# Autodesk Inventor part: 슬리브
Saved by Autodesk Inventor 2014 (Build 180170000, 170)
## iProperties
Created: 2026-09
Part Number: 슬리브
Material: 일반
Document SubType Name: Modeling
Designer: dg
Density: 1 g/cm^3
Appearance: 기본값
Author: dg
Author: jhkim
Creation Date: 2026-08-27
Sending System: Autodesk Inventor 2027
Preprocessor: ST-DEVELOPER v20.1
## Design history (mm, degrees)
node "슬리브1"
node "솔리드1"
node "기준1"
